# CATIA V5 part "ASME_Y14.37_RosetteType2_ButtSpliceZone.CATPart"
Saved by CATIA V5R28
Part number: 333X3333-303
Revision: --
Nomenclature: ASME_Y14.37_RosetteType2
Bounding box of the stored display mesh (mm): x -182.712 to 149.059, y -701.798 to 651.612, z 2.54 to 91.639
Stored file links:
  C:\Users\jvl2147\Documents\AP242 testing\Composite Example Parts for PER\ASME_Y14.37_RosetteType2_ButtSpliceZone.CATPart
  \\NW\Data\MSE-Composites\ASME Y14.37\ASME Y-14.37_COMPOSITES.CATMaterial
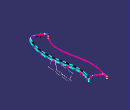
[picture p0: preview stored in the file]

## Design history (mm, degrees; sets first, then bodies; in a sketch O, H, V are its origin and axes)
AxisSystem1 "ROSETTE COORDINATE SYSTEM": origin (-72.9205, -637.9645, 93.98), X (0.5026, 0.8645, 0), Y (-0.8645, 0.5026, 0), Z (0, 0, 1)
CompParametersFeature1 "CATCoParametersFeatName": Value 0, Value 45, Value -45, Value 90
CompEOPGroupFeature1 "CATCoEOPGroupFeatName"
CompStacking1 "Stacking"
CompIsoThickAreasGroup1 "CATCoIsoThickAreasGroupFeatName": RefAddThickness 0
TTRSSet1
f4a2d38f3ddc11d3a929006094b99c4b_11 "CATTPSSet"
CompReviewTools1 "Review tools"
Set1 "CONSTRUCTION GEOMETRY"
  Set2 "CONSTRUCTION - LAMINATE REFERENCE SURFACE"
    Sketch1 on xy-plane, origin (0, 0, 0), H (1, 0, 0), V (0, 1, 0)
      spline S1 through (-79.505, -649.09) (21.2912, -260.3998) (-51.6257, 228.8061) (37.963, 602.845)
    Plane1: type Normal, Curve Sketch1, RefPoint vertex of Sketch1, Ratio 0
    Sketch2 on Plane1, origin (-464.3095, -417.3341, 0), H (-0.8566, 0.5159, 0), V (0, 0, 1)
      line L1 (-525.4052, 91.6386) -> (-373.0052, 91.6386)
      line L2 (-322.2052, 40.8386) -> (-322.2052, 0)
      line L3 (-576.2052, 0) -> (-576.2052, 40.8386)
      reference projected point E1 (-449.2052, 0) from vertex of Sketch1
      reference projected point E2 (-449.2052, 0) from vertex of Sketch1
      arc A1 centre (-373.0052, 40.8386) radius 50.8 from (-373.0052, 91.6386) to (-322.2052, 40.8386) cw
      arc A2 centre (-525.4052, 40.8386) radius 50.8 from (-576.2052, 40.8386) to (-525.4052, 91.6386) cw
      distance E1 L2 = 127
      distance E2 L3 = 127
      radius A1 = 50.8
      radius A2 = 50.8
      horizontal: L1 H
      vertical: L2 V, L3 V
      tangency: A1 L1, A1 L2, A2 L3, A2 L1
    Sweep1: type Unspec, Profile Sketch2, Guide Sketch1
  Set3 "CONSTRUCTION - PLIES EOPS"
    Plane2: type Normal, Curve Sketch1, RefPoint vertex of Sketch1, Ratio 0
    Plane3: type Normal, Curve Sketch1, RefPoint {point type OnCurve, Support Sketch1, Length 1118.262}, Ratio 0.99
    Plane4: type Normal, Curve Sketch1, Ratio 0.01
    Intersect1: ToIntersect1 Plane3, ToIntersect2 Sweep1
    Intersect2: ToIntersect1 Sweep1, ToIntersect2 Plane4
    Plane5: type Offset, RefPlane xy-plane, Offset 2.54
    Intersect3: ToIntersect1 Plane5, ToIntersect2 Join1
    Near1: MultiElement Intersect3, ReferenceElement edge of Sweep1
    Near2: MultiElement Intersect3, ReferenceElement edge of Sweep1
  Set4 "CONSTRUCTION - ROSETTE COORDINATE SYSTEM"
    Intersect4: ToIntersect1 Plane4, ToIntersect2 Project2
    Line1: type Tangency, RefPoint Intersect4, Curve Project2, Start 0, End 25.4
    Plane6: type Offset, RefPlane xy-plane, Offset 93.98
    Project1 "PROJECT": ToProject Sketch1, Support Join1, Direction xy-plane
  Set5 "CONSTRUCTION - ROSETTE TRANSFORMS"
    Line2 "Ply.1_Rosette_transfer_X": type Tangency, RefPoint {point type OnCurve, Support Project2, Length 288.56}, Curve Project2, Support Join1, Start 0, End 25.4
    Line3 "Ply.1_Rosette_transfer_X.Renamed": type Tangency, RefPoint {point type OnCurve, Support Project2, Length 536.186}, Curve Project2, Support Join1, Start 25.4, End 0
    Line4 "Ply.1_Rosette_transfer_X.Renamed": type Tangency, RefPoint {point type OnCurve, Support Project2, Length 783.62}, Curve Project2, Support Join1, Start 25.4, End 0
    Line5 "Ply.1_Rosette_transfer_X.Renamed": type Tangency, RefPoint {point type OnCurve, Support Project2, Length 1274.71}, Curve Project2, Support Join1, Start 25.4, End 0
    Line6 "Ply.1_Rosette_transfer_X.Renamed": type Tangency, RefPoint {point type OnCurve, Support Project2, Length 1017.245}, Curve Project2, Support Join1, Start 25.4, End 0
    AxisSystem2 "ROSETTE COORDINATE SYSTEM": origin (16.8931, -379.3831, 93.98), X (0.1242, 0.9923, 0), Y (-0.9923, 0.1242, 0), Z (0, 0, 1)
    AxisSystem3 "ROSETTE COORDINATE SYSTEM.Renamed": origin (7.1166, -132.8437, 93.98), X (-0.1632, 0.9866, 0), Y (-0.9866, -0.1632, 0), Z (0, 0, 1)
    AxisSystem4 "ROSETTE COORDINATE SYSTEM.Renamed1": origin (-38.9217, 110.2518, 93.98), X (-0.1571, 0.9876, 0), Y (-0.9876, -0.1571, 0), Z (0, 0, 1)
    AxisSystem5 "ROSETTE COORDINATE SYSTEM.Renamed2": origin (29.3229, 586.9432, 93.98), X (0.4677, 0.8839, 0), Y (-0.8839, 0.4677, 0), Z (0, 0, 1)
    AxisSystem6 "ROSETTE COORDINATE SYSTEM.Renamed3": origin (-47.995, 342.9553, 93.98), X (0.1137, 0.9935, 0), Y (-0.9935, 0.1137, 0), Z (0, 0, 1)
    Point1: type OnSurface, Support Join1, Length 362.156, Direction (-0.4364, -0.3881, 0.8118)
    Line7: type Normal, RefPoint Point1, RefSkin Join1, Start 254, End 0
  Plane7: type Offset, RefPlane YZ plane of AxisSystem2, Offset 0
  Circle1: type CtrRad, Start 0, End 180, Center {point type OnSurface, Support Join1, Length 336.531, Direction (0.5738, 0.5102, 0.6407)}, Support Join1, Radius 50.8, FirstDirection (1, 0, 0)
  CurvePar1: Offset Near1, Support Join1, Offset2 0, Offset1 50.8
Set6 "ENGINEERING GEOMETRY"
  Set7 "LAMINATE REFERENCE SURFACE"
    Join1 "LAMINATE REFERENCE SURFACE": Elements Sweep1
  Set8 "GUIDE CURVE - ZERO DEGREE ORIENTATION"
    Project2 "GUIDE CURVE - 0°": ToProject Sketch1, Support Plane6
Body1 (main body)
Body2 "-303"
  CompIsoThickAreasSolid1 "Area Solid.1": IsoAreasGroup CompIsoThickAreasGroup1
Set9 "Workaround For FT&A"
  Split1 "Surface For FT&A": ToCut Join1
Set10 "Workaround For FT&A"
  Split2 "Surface For FT&A": ToCut Join1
